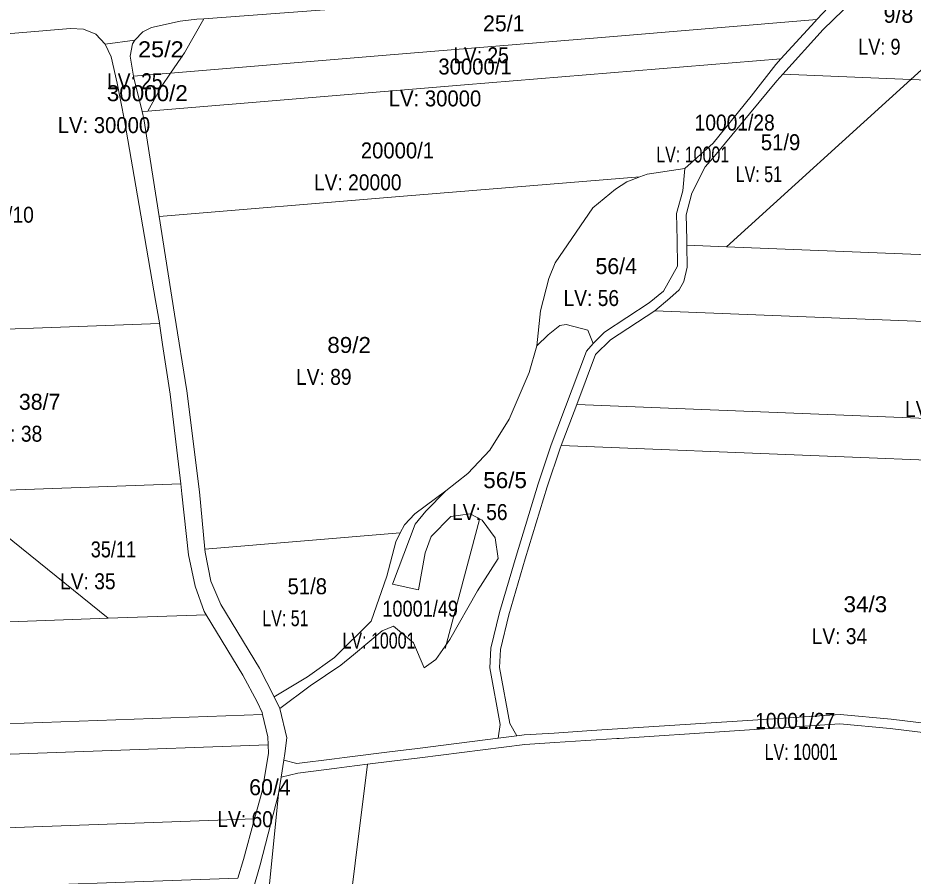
# Model space of a CAD drawing. Extents: x -713758 to -711119, y -1123067 to -1120789.
# Drawn here: x -712790 to -712228, y -1122197 to -1121659 of the extents above; entities that cross this region are included whole.
import ezdxf
from ezdxf.enums import TextEntityAlignment as Align

# ---------------------------------------------------------------- set-up
doc = ezdxf.new("R2010")
doc.units = 0
doc.header["$LTSCALE"] = 4
doc.layers.add('1', color=7, linetype='Continuous', lineweight=13)
doc.layers.add('10', color=7, linetype='Continuous', lineweight=13)
doc.layers.add('11', color=7, linetype='Continuous')
doc.layers.add('13', color=7, linetype='Continuous')

msp = doc.modelspace()

# ---------------------------------------------------------------- linework, layer by layer
at = {"layer": '1'}
msp.add_line((-712500.27, -1121973.65), (-712521.83, -1122054.58), dxfattribs=at)
at = {"layer": '10'}
for points in [[(-712229.88, -1121697.85), (-712138.38, -1121614.8), (-712059.59, -1121602.17), (-712016.1, -1121591.07), (-711982.28, -1121581.75), (-711923.15, -1121565.46), (-711766.99, -1121519.55), (-711769.17, -1121541.36), (-711785.23, -1121585.51), (-711791.73, -1121600.27), (-711820.89, -1121675.91), (-711835.92, -1121713.6), (-712032.9, -1121705.73)], [(-712310.25, -1121694.64), (-712229.88, -1121697.85), (-712138.38, -1121614.8), (-712201.33, -1121620.73), (-712241.17, -1121624.1), (-712284.89, -1121666.46)], [(-712693.92, -1121693.86), (-712685.27, -1121681.19), (-712673.12, -1121659.8), (-712535.55, -1121649.68), (-712434.68, -1121640.83), (-712350.1, -1121632.59), (-712255.74, -1121625.24), (-712288.77, -1121660.36), (-712423.82, -1121671.53), (-712558.87, -1121682.69)], [(-712719.26, -1121683.24), (-712717.81, -1121675.51), (-712716.34, -1121673.15), (-712711.27, -1121667.93), (-712705.83, -1121665.37), (-712687.79, -1121661.3), (-712677.41, -1121660.12), (-712673.12, -1121659.8), (-712685.27, -1121681.19), (-712693.92, -1121693.86), (-712717.04, -1121695.77)], [(-712708.07, -1121717.7), (-712699.62, -1121702.22), (-712693.92, -1121693.86), (-712558.87, -1121682.69), (-712423.82, -1121671.53), (-712288.77, -1121660.36), (-712290.05, -1121661.72), (-712311.31, -1121684.88), (-712509.69, -1121701.29)], [(-712880.84, -1121755.13), (-712866.01, -1121753.2), (-712853.12, -1121749.15), (-712844, -1121745.94), (-712842.34, -1121739.38), (-712842.12, -1121722.83), (-712842.97, -1121711.59), (-712846.26, -1121702.25), (-712856.88, -1121691.21), (-712852.69, -1121674.34), (-712811.56, -1121670.57), (-712756.64, -1121665.93), (-712748.52, -1121666.41), (-712740.68, -1121669.42), (-712734.88, -1121675.75), (-712731.11, -1121683.63), (-712727.43, -1121700.1), (-712722.81, -1121723.55), (-712713.57, -1121776.81), (-712703.43, -1121836.37), (-712700.91, -1121850.47), (-712700.85, -1121850.86), (-712870.42, -1121857.05), (-712876.71, -1121787.4)], [(-712711.78, -1121718.01), (-712708.07, -1121717.7), (-712509.69, -1121701.29), (-712311.31, -1121684.88), (-712314.6, -1121688.46), (-712330, -1121708.27), (-712353.76, -1121737.88), (-712371.61, -1121753.63), (-712395.26, -1121757.14), (-712399.72, -1121758.86), (-712550.41, -1121771.32), (-712701.09, -1121783.79), (-712710.7, -1121722.53)], [(-712717.04, -1121695.77), (-712693.92, -1121693.86), (-712699.62, -1121702.22), (-712708.07, -1121717.7), (-712711.78, -1121718.01), (-712716.86, -1121696.76)], [(-712370.79, -1121782.67), (-712370.4, -1121798.44), (-712370.34, -1121801.72), (-712345.4, -1121802.72), (-712229.88, -1121697.85), (-712310.25, -1121694.64), (-712313.92, -1121698.72), (-712342.17, -1121732.73), (-712354.04, -1121747.26), (-712358.89, -1121752.57), (-712367.1, -1121769.23)], [(-712345.4, -1121802.72), (-712182.69, -1121809.23), (-712019.97, -1121815.74), (-711857.26, -1121822.25), (-711854.58, -1121793.79), (-711851.16, -1121773.83), (-711848.33, -1121765.03), (-711850.53, -1121760.95), (-711852.87, -1121751.59), (-711845.69, -1121738.11), (-711835.92, -1121713.6), (-712032.9, -1121705.73), (-712229.88, -1121697.85)], [(-712464.26, -1121864.8), (-712457.22, -1121857.89), (-712449.82, -1121852.18), (-712445.97, -1121851.4), (-712432.46, -1121854.9), (-712429.13, -1121863.41), (-712421.91, -1121856.34), (-712394.02, -1121837.96), (-712384.91, -1121830.47), (-712376.08, -1121814.99), (-712376.4, -1121798.52), (-712376.81, -1121781.93), (-712372.89, -1121767.64), (-712371.61, -1121753.63), (-712395.26, -1121757.14), (-712399.72, -1121758.86), (-712407.91, -1121762.02), (-712414.93, -1121766.68), (-712429.16, -1121778.33), (-712452.92, -1121812.8), (-712456.78, -1121822.69), (-712462.11, -1121842.92)], [(-712701.09, -1121783.79), (-712550.41, -1121771.32), (-712399.72, -1121758.86), (-712407.91, -1121762.02), (-712414.93, -1121766.68), (-712429.16, -1121778.33), (-712452.92, -1121812.8), (-712456.78, -1121822.69), (-712462.11, -1121842.92), (-712464.26, -1121864.8), (-712469.19, -1121881.45), (-712481.75, -1121910.79), (-712493.76, -1121930.22), (-712507.66, -1121944.82), (-712521.31, -1121955.62), (-712540.86, -1121970.05), (-712547.32, -1121977.03), (-712549.91, -1121982.02), (-712672.5, -1121992.16), (-712675.83, -1121956.22), (-712683.75, -1121893.08), (-712691.51, -1121844.88)], [(-712390.45, -1121842.79), (-712216.37, -1121849.75), (-712042.3, -1121856.72), (-711868.22, -1121863.68), (-711863.56, -1121851.73), (-711857.61, -1121825.96), (-711857.26, -1121822.25), (-712019.97, -1121815.74), (-712182.69, -1121809.23), (-712345.4, -1121802.72), (-712370.34, -1121801.72), (-712370.07, -1121815.62), (-712372.12, -1121824.42), (-712375.18, -1121829.75), (-712381, -1121835.02)], [(-712439.32, -1121901.5), (-712266.67, -1121908.4), (-712094.01, -1121915.31), (-711921.36, -1121922.21), (-711905.03, -1121907.27), (-711897.42, -1121901.24), (-711883.6, -1121889.47), (-711879.9, -1121886.06), (-711871.58, -1121872.29), (-711868.22, -1121863.68), (-712042.3, -1121856.72), (-712216.37, -1121849.75), (-712390.45, -1121842.79), (-712418.13, -1121861.03), (-712427.59, -1121870.3)], [(-712870.42, -1121857.05), (-712700.85, -1121850.86), (-712698.93, -1121864.01), (-712694.13, -1121895.03), (-712687.55, -1121951.31), (-712831.1, -1121956.54)], [(-712625.52, -1122092.02), (-712606.48, -1122077.83), (-712587.12, -1122064.98), (-712579.21, -1122058.5), (-712561.31, -1122043.36), (-712554.13, -1122040.44), (-712541.63, -1122050.98), (-712535.02, -1122066.53), (-712527.66, -1122061.43), (-712518.9, -1122048.94), (-712501.57, -1122018.31), (-712488.62, -1121998.01), (-712490.37, -1121985.13), (-712498.55, -1121974.08), (-712506.15, -1121970.07), (-712518.19, -1121971.74), (-712530.57, -1121984.26), (-712534.41, -1121994.53), (-712538.53, -1122017.82), (-712554.88, -1122014.28), (-712540.54, -1121976.66), (-712533.93, -1121968.44), (-712521.31, -1121955.62), (-712507.66, -1121944.82), (-712493.76, -1121930.22), (-712481.75, -1121910.79), (-712469.19, -1121881.45), (-712464.26, -1121864.8), (-712457.22, -1121857.89), (-712449.82, -1121852.18), (-712445.97, -1121851.4), (-712432.46, -1121854.9), (-712429.13, -1121863.41), (-712433.21, -1121868.19), (-712455.27, -1121926.87), (-712463.59, -1121951.4), (-712477.36, -1121996.6), (-712487.71, -1122031.98), (-712493.11, -1122054.33), (-712493.85, -1122066.7), (-712487.33, -1122102.14), (-712488.61, -1122110.76), (-712539.19, -1122117.12), (-712556.73, -1122119.34), (-712584.87, -1122122.88), (-712591.12, -1122123.67), (-712614.83, -1122126.66), (-712622.97, -1122124.42), (-712622.35, -1122120.37), (-712620.99, -1122110.55)], [(-712449, -1121927.24), (-712282.24, -1121933.91), (-712115.49, -1121940.58), (-711948.74, -1121947.25), (-711921.36, -1121922.21), (-712094.01, -1121915.31), (-712266.67, -1121908.4), (-712439.32, -1121901.5)], [(-712831.1, -1121956.54), (-712687.55, -1121951.31), (-712686.83, -1121957.49), (-712682.74, -1121995.84), (-712678.59, -1122015.49), (-712672.75, -1122031.36), (-712671.57, -1122033.31), (-712732.93, -1122035.55)], [(-712946.78, -1122043.35), (-712932.04, -1122023.99), (-712922.26, -1122006.03), (-712914.44, -1121978.97), (-712918.75, -1121959.74), (-712831.1, -1121956.54), (-712732.93, -1122035.55), (-712839.85, -1122039.45)], [(-712629.07, -1122084.81), (-712608.13, -1122072.31), (-712591.13, -1122060.24), (-712568.22, -1122037.4), (-712558.33, -1122009.12), (-712552.81, -1121987.61), (-712549.91, -1121982.02), (-712547.32, -1121977.03), (-712540.86, -1121970.05), (-712521.31, -1121955.62), (-712533.93, -1121968.44), (-712540.54, -1121976.66), (-712554.88, -1122014.28), (-712538.53, -1122017.82), (-712534.41, -1121994.53), (-712530.57, -1121984.26), (-712518.19, -1121971.74), (-712506.15, -1121970.07), (-712498.55, -1121974.08), (-712490.37, -1121985.13), (-712488.62, -1121998.01), (-712501.57, -1122018.31), (-712518.9, -1122048.94), (-712527.66, -1122061.43), (-712535.02, -1122066.53), (-712541.63, -1122050.98), (-712554.13, -1122040.44), (-712561.31, -1122043.36), (-712579.21, -1122058.5), (-712587.12, -1122064.98), (-712606.48, -1122077.83), (-712625.52, -1122092.02)], [(-712672.5, -1121992.16), (-712549.91, -1121982.02), (-712552.81, -1121987.61), (-712558.33, -1122009.12), (-712568.22, -1122037.4), (-712591.13, -1122060.24), (-712608.13, -1122072.31), (-712629.07, -1122084.81), (-712638.18, -1122066.77), (-712662.3, -1122027.04), (-712668.69, -1122012.24), (-712672.31, -1121994.19)], [(-713004.26, -1122109.23), (-713001.65, -1122100.46), (-712997.1, -1122089.99), (-712986.87, -1122077.93), (-712961.95, -1122063.28), (-712946.78, -1122043.35), (-712839.85, -1122039.45), (-712732.93, -1122035.55), (-712671.57, -1122033.31), (-712648.66, -1122071.25), (-712639.54, -1122087.86), (-712636.58, -1122094.53), (-712636.27, -1122095.8), (-712820.27, -1122102.52)], [(-713010.04, -1122128.66), (-712863.78, -1122123.32), (-712748.22, -1122119.11), (-712632.65, -1122114.89), (-712632.85, -1122109.87), (-712636.27, -1122095.8), (-712820.27, -1122102.52), (-713004.26, -1122109.23)], [(-713022.45, -1122175.1), (-713017.89, -1122157.12), (-712863.04, -1122151.46), (-712863.78, -1122123.32), (-712748.22, -1122119.11), (-712632.65, -1122114.89), (-712632.44, -1122120.31), (-712636.42, -1122143.91), (-712641.22, -1122161.19), (-712831.84, -1122168.14)], [(-712638.37, -1122267.02), (-712626.26, -1122145.69), (-712624.64, -1122135.22), (-712614.24, -1122132.63), (-712589.67, -1122129.53), (-712583.46, -1122128.75), (-712570.37, -1122127.1), (-712593.46, -1122311.4), (-712606.26, -1122300.57), (-712615.39, -1122292.19), (-712623.54, -1122284.42), (-712626.92, -1122281.37), (-712632.38, -1122274.66), (-712635.85, -1122270.26)], [(-712648.93, -1122241.9), (-712647.32, -1122249.66), (-712642.44, -1122261.77), (-712638.37, -1122267.02), (-712626.26, -1122145.69), (-712637.78, -1122190), (-712648.55, -1122227.95)], [(-713028.86, -1122212.11), (-712840.29, -1122205.23), (-712651.72, -1122198.35), (-712648.29, -1122186.66), (-712641.22, -1122161.19), (-712831.84, -1122168.14), (-713022.45, -1122175.1), (-713025.76, -1122188.12), (-713028.85, -1122211.11)]]:
    msp.add_lwpolyline(points, close=True, dxfattribs=at)
for points in [[(-712201.33, -1121620.73), (-712241.17, -1121624.1), (-712255.74, -1121625.24), (-712350.1, -1121632.59), (-712434.68, -1121640.83), (-712535.55, -1121649.68), (-712673.12, -1121659.8), (-712677.41, -1121660.12), (-712687.79, -1121661.3), (-712705.83, -1121665.37), (-712711.27, -1121667.93), (-712716.34, -1121673.15), (-712734.88, -1121675.75), (-712740.68, -1121669.42), (-712748.52, -1121666.41), (-712756.64, -1121665.93), (-712811.56, -1121670.57)], [(-712255.74, -1121625.24), (-712288.77, -1121660.36), (-712290.05, -1121661.72), (-712311.31, -1121684.88), (-712314.6, -1121688.46), (-712330, -1121708.27), (-712353.76, -1121737.88), (-712371.61, -1121753.63), (-712372.89, -1121767.64), (-712376.81, -1121781.93), (-712376.4, -1121798.52), (-712376.08, -1121814.99), (-712384.91, -1121830.47), (-712394.02, -1121837.96), (-712421.91, -1121856.34), (-712429.13, -1121863.41), (-712433.21, -1121868.19), (-712455.27, -1121926.87), (-712463.59, -1121951.4), (-712477.36, -1121996.6), (-712487.71, -1122031.98), (-712493.11, -1122054.33), (-712493.85, -1122066.7), (-712487.33, -1122102.14), (-712488.61, -1122110.76), (-712476.85, -1122109.28), (-712481.33, -1122101.6), (-712487.82, -1122066.33), (-712487.15, -1122055.22), (-712481.91, -1122033.51), (-712471.62, -1121998.36), (-712457.88, -1121953.24), (-712449.61, -1121928.87), (-712449, -1121927.24), (-712439.32, -1121901.5), (-712427.59, -1121870.3), (-712418.13, -1121861.03), (-712390.45, -1121842.79), (-712381, -1121835.02), (-712375.18, -1121829.75), (-712372.12, -1121824.42), (-712370.07, -1121815.62), (-712370.34, -1121801.72), (-712370.4, -1121798.44), (-712370.79, -1121782.67), (-712367.1, -1121769.23), (-712358.89, -1121752.57), (-712354.04, -1121747.26), (-712342.17, -1121732.73), (-712313.92, -1121698.72), (-712310.25, -1121694.64), (-712284.89, -1121666.46), (-712241.17, -1121624.1)], [(-712648.55, -1122227.95), (-712637.78, -1122190), (-712626.26, -1122145.69), (-712624.64, -1122135.22), (-712622.97, -1122124.42), (-712622.35, -1122120.37), (-712620.99, -1122110.55), (-712625.52, -1122092.02), (-712629.07, -1122084.81), (-712638.18, -1122066.77), (-712662.3, -1122027.04), (-712668.69, -1122012.24), (-712672.31, -1121994.19), (-712672.5, -1121992.16), (-712675.83, -1121956.22), (-712683.75, -1121893.08), (-712691.51, -1121844.88), (-712701.09, -1121783.79), (-712710.7, -1121722.53), (-712711.78, -1121718.01), (-712716.86, -1121696.76), (-712717.04, -1121695.77), (-712719.26, -1121683.24), (-712717.81, -1121675.51), (-712716.34, -1121673.15), (-712734.88, -1121675.75)], [(-712734.88, -1121675.75), (-712731.11, -1121683.63), (-712727.43, -1121700.1), (-712722.81, -1121723.55), (-712713.57, -1121776.81), (-712703.43, -1121836.37), (-712700.91, -1121850.47), (-712700.85, -1121850.86), (-712698.93, -1121864.01), (-712694.13, -1121895.03), (-712687.55, -1121951.31), (-712686.83, -1121957.49), (-712682.74, -1121995.84), (-712678.59, -1122015.49), (-712672.75, -1122031.36), (-712671.57, -1122033.31), (-712648.66, -1122071.25), (-712639.54, -1122087.86), (-712636.58, -1122094.53), (-712636.27, -1122095.8), (-712632.85, -1122109.87), (-712632.65, -1122114.89), (-712632.44, -1122120.31), (-712636.42, -1122143.91), (-712641.22, -1122161.19), (-712648.29, -1122186.66), (-712651.72, -1122198.35)], [(-712199.3, -1122103.98), (-712242.32, -1122098.75), (-712274.28, -1122095.81), (-712328.86, -1122099.36), (-712430.11, -1122105.96), (-712453.47, -1122107.48), (-712472.36, -1122108.72), (-712476.85, -1122109.28), (-712481.33, -1122101.6), (-712487.82, -1122066.33), (-712487.15, -1122055.22), (-712481.91, -1122033.51), (-712471.62, -1121998.36), (-712457.88, -1121953.24), (-712449.61, -1121928.87), (-712449, -1121927.24), (-712282.24, -1121933.91), (-712115.49, -1121940.58)], [(-712199.3, -1122103.98), (-712242.32, -1122098.75), (-712274.28, -1122095.81), (-712328.86, -1122099.36), (-712430.11, -1122105.96), (-712453.47, -1122107.48), (-712472.36, -1122108.72), (-712476.85, -1122109.28), (-712488.61, -1122110.76), (-712539.19, -1122117.12), (-712556.73, -1122119.34), (-712584.87, -1122122.88), (-712591.12, -1122123.67), (-712614.83, -1122126.66), (-712622.97, -1122124.42), (-712624.64, -1122135.22), (-712614.24, -1122132.63), (-712589.67, -1122129.53), (-712583.46, -1122128.75), (-712570.37, -1122127.1), (-712555.16, -1122125.19), (-712537.6, -1122122.97), (-712471.79, -1122114.69), (-712453.08, -1122113.47), (-712414.27, -1122110.94), (-712412.73, -1122110.84), (-712274.36, -1122101.82), (-712242.94, -1122104.72), (-712201.72, -1122109.73)], [(-712593.46, -1122311.4), (-712570.37, -1122127.1), (-712555.16, -1122125.19), (-712537.6, -1122122.97), (-712471.79, -1122114.69), (-712453.08, -1122113.47), (-712414.27, -1122110.94), (-712412.73, -1122110.84), (-712274.36, -1122101.82), (-712242.94, -1122104.72), (-712201.72, -1122109.73), (-712072.6, -1122125.44), (-712066.77, -1122126.32), (-711992.36, -1122135.84), (-711796.12, -1122160.95), (-711751.06, -1122165.34), (-711740.44, -1122174.1), (-711748.73, -1122189.21), (-711756.25, -1122209.29)]]:
    msp.add_lwpolyline(points, dxfattribs=at)

# ---------------------------------------------------------------- texts
at = {"layer": '11'}
for s, p in [('25/1', (-712485.061, -1121667.71)), ('9/8', (-712237.69, -1121662.36)), ('56/4', (-712414.57, -1121819.86)), ('38/7', (-712775.97, -1121904.89)), ('60/4', (-712631.64, -1122146.45))]:
    msp.add_text(s, height=10, dxfattribs=at).set_placement(p, align=Align.CENTER)
for s, width, p in [('25/2', 1.1, (-712700, -1121683.96)), ('30000/1', 0.95, (-712503.09, -1121694.75)), ('30000/2', 1.05, (-712708.5, -1121711.47)), ('10001/28', 0.9, (-712340.33, -1121729.9)), ('51/9', 0.95, (-712311.58, -1121742.23)), ('20000/1', 0.95, (-712551.701, -1121747.35)), ('10002/10', 0.9, (-712804.71, -1121787.64)), ('89/2', 1.05, (-712581.98, -1121869.28)), ('56/5', 1.05, (-712484.231, -1121953.99)), ('35/11', 0.85, (-712729.73, -1121997.39)), ('51/8', 0.95, (-712608.22, -1122020.52)), ('34/3', 1.05, (-712258.41, -1122031.77)), ('10001/49', 0.85, (-712537.451, -1122034.54)), ('10001/27', 0.9, (-712302.351, -1122104.88))]:
    msp.add_text(s, height=10, dxfattribs=dict(at, width=width)).set_placement(p, align=Align.CENTER)
at = {"layer": '13'}
for s, width, p in [('LV: 9 ', 0.85, (-712248.063, -1121682.36)), ('LV: 25 ', 0.9, (-712497.642, -1121687.71)), ('LV: 25 ', 0.9, (-712714.69, -1121703.96)), ('LV: 30000 ', 0.95, (-712526.378, -1121714.75)), ('LV: 30000 ', 0.95, (-712733.897, -1121731.47)), ('LV: 10001 ', 0.75, (-712365.225, -1121749.9)), ('LV: 51 ', 0.75, (-712323.793, -1121762.23)), ('LV: 20000 ', 0.9, (-712574.922, -1121767.35)), ('LV: 56 ', 0.9, (-712428.523, -1121839.86)), ('LV: 89 ', 0.9, (-712596.201, -1121889.28)), ('LV: 38 ', 0.9, (-712214.463, -1121909.48)), ('LV: 38 ', 0.9, (-712790.057, -1121924.89)), ('LV: 56 ', 0.9, (-712498.418, -1121973.99)), ('LV: 35 ', 0.9, (-712744.084, -1122017.39)), ('LV: 51 ', 0.75, (-712620.534, -1122040.52)), ('LV: 34 ', 0.9, (-712273, -1122051.77)), ('LV: 10001 ', 0.75, (-712561.876, -1122054.54)), ('LV: 10001 ', 0.75, (-712297.274, -1122124.33)), ('LV: 60 ', 0.9, (-712645.493, -1122166.45))]:
    msp.add_text(s, height=10, dxfattribs=dict(at, width=width)).set_placement(p, align=Align.CENTER)

doc.saveas('drawing.dxf')
